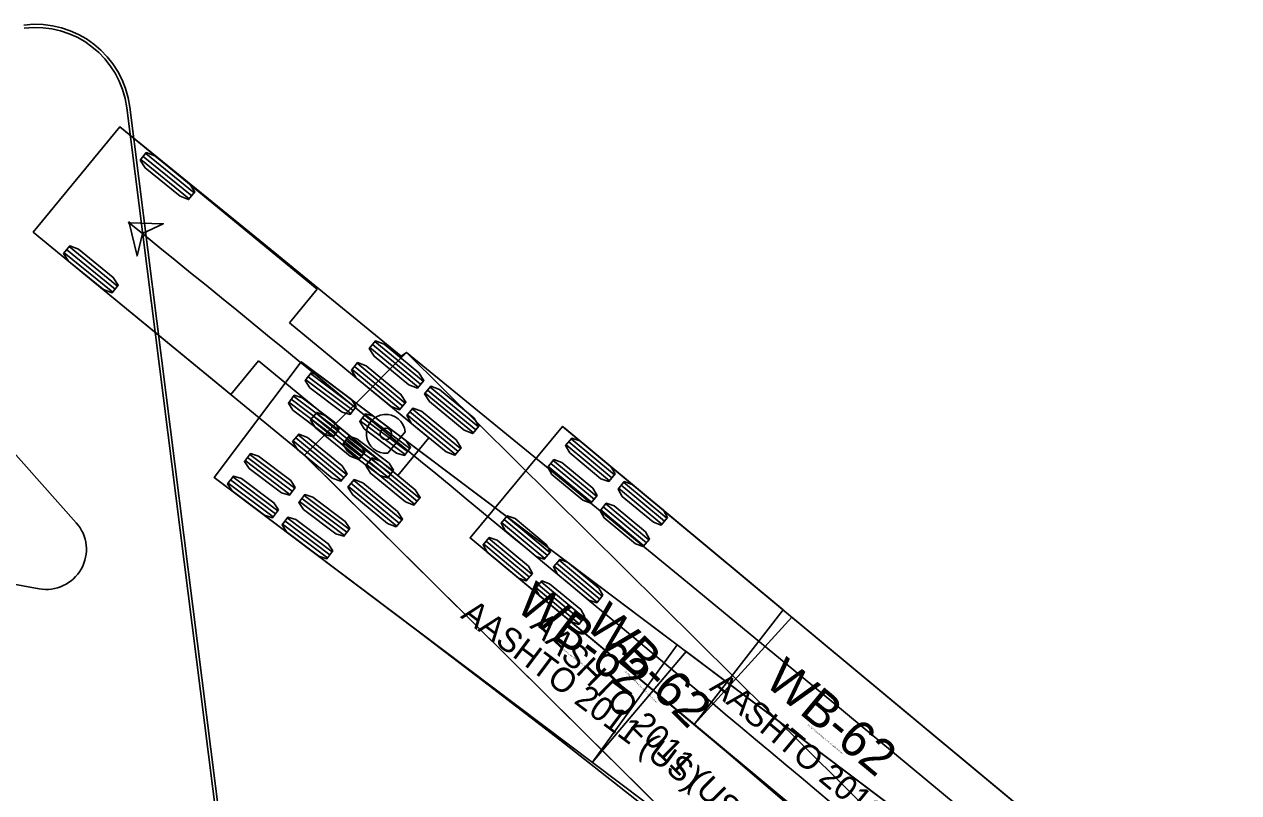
# Model space of a CAD drawing. Extents: x 2096670 to 2098561, y 684033 to 689893.
# Drawn here: x 2097513.6 to 2097584.9, y 686082 to 686127.1 of the extents above; entities that cross this region are included whole.
import ezdxf

# ---------------------------------------------------------------- set-up
doc = ezdxf.new("R2010")
doc.units = 0
doc.layers.add('Old_Level_63', color=7, linetype='Continuous')
doc.layers.add('Prop Sign E Keep Right CELL', color=7, linetype='Continuous')

# ---------------------------------------------------------------- blocks, each defined once
blk = doc.blocks.new('R4_7A')
at = {"layer": 'Prop Sign E Keep Right CELL'}
for points in [[(2.8414, 5.1147), (4.1564, 7.0314), (5.4711, 5.1147)], [(2.8414, 5.1147), (4.1564, 7.0314), (5.4711, 5.1147)], [(2.8414, 5.1147), (4.1564, 7.0314), (5.4711, 5.1147)], [(5.2458, 4.8106), (4.6564, 4.9975), (4.6564, 4.3867)], [(5.2458, 4.8106), (4.6564, 4.9975), (4.6564, 4.3867)], [(5.2458, 4.8106), (4.6564, 4.9975), (4.6564, 4.3867)]]:
    blk.add_lwpolyline(points, dxfattribs=at)
blk.add_arc((5.3062, 5.0014), 0.2, 252.39904, 34.44923, dxfattribs=at)
blk.add_arc((5.3062, 5.0014), 0.2, 252.39904, 34.44923, dxfattribs=at)
blk.add_arc((5.3062, 5.0014), 0.2, 252.39904, 34.44923, dxfattribs=at)

msp = doc.modelspace()

# ---------------------------------------------------------------- linework, layer by layer
at = {"layer": 'Old_Level_63'}
for p, q in [((2097519.23, 686121.097), (2097514.149, 686114.918)), ((2097530.816, 686111.569), (2097519.23, 686121.097)), ((2097520.748, 686119.537), (2097523.594, 686117.226)), ((2097520.459, 686119.182), (2097523.305, 686116.87)), ((2097520.604, 686119.359), (2097523.45, 686117.048)), ((2097514.149, 686114.918), (2097525.735, 686105.39)), ((2097514.149, 686114.918), (2097514.149, 686114.918)), ((2097516.109, 686113.885), (2097518.955, 686111.573)), ((2097516.253, 686114.063), (2097519.099, 686111.751)), ((2097515.964, 686113.707), (2097518.811, 686111.395)), ((2097529.186, 686109.587), (2097530.816, 686111.569)), ((2097537.373, 686102.854), (2097529.186, 686109.587)), ((2097533.907, 686108.137), (2097536.739, 686105.808)), ((2097534.052, 686108.314), (2097536.884, 686105.985)), ((2097534.198, 686108.491), (2097537.03, 686106.162)), ((2097536.055, 686107.859), (2097530.074, 686101.82)), ((2097570.158, 686074.08), (2097536.055, 686107.859)), ((2097529.882, 686107.308), (2097524.771, 686100.517)), ((2097525.735, 686105.39), (2097527.365, 686107.372)), ((2097527.365, 686107.372), (2097535.552, 686100.64)), ((2097568.235, 686078.446), (2097529.882, 686107.308)), ((2097532.859, 686106.863), (2097535.691, 686104.534)), ((2097533.004, 686107.04), (2097535.836, 686104.711)), ((2097533.15, 686107.217), (2097535.982, 686104.888)), ((2097532.784, 686104.264), (2097530.147, 686106.248)), ((2097532.922, 686104.447), (2097530.285, 686106.431)), ((2097533.06, 686104.63), (2097530.423, 686106.614)), ((2097532.068, 686103.312), (2097529.431, 686105.296)), ((2097537.151, 686105.47), (2097539.983, 686103.141)), ((2097537.296, 686105.647), (2097540.128, 686103.318)), ((2097537.442, 686105.824), (2097540.274, 686103.495)), ((2097531.792, 686102.945), (2097529.155, 686104.93)), ((2097531.93, 686103.128), (2097529.293, 686105.113)), ((2097530.455, 686103.941), (2097533.288, 686101.612)), ((2097530.601, 686104.118), (2097533.433, 686101.789)), ((2097530.747, 686104.295), (2097533.579, 686101.966)), ((2097536.118, 686102.042), (2097533.481, 686104.026)), ((2097536.256, 686102.225), (2097533.619, 686104.209)), ((2097536.102, 686104.195), (2097538.935, 686101.866)), ((2097536.248, 686104.372), (2097539.08, 686102.043)), ((2097536.394, 686104.549), (2097539.226, 686102.22)), ((2097535.98, 686101.859), (2097533.343, 686103.843)), ((2097534.951, 686101.943), (2097535.978, 686103.191)), ((2097545.219, 686103.511), (2097539.785, 686096.975)), ((2097582.131, 686072.828), (2097545.219, 686103.511)), ((2097529.407, 686102.666), (2097532.239, 686100.337)), ((2097529.553, 686102.843), (2097532.385, 686100.514)), ((2097529.699, 686103.02), (2097532.531, 686100.691)), ((2097534.988, 686100.54), (2097532.351, 686102.524)), ((2097535.126, 686100.723), (2097532.489, 686102.708)), ((2097535.264, 686100.906), (2097532.627, 686102.891)), ((2097535.552, 686100.64), (2097537.373, 686102.854)), ((2097547.971, 686100.33), (2097545.433, 686102.439)), ((2097548.117, 686100.506), (2097545.58, 686102.615)), ((2097548.264, 686100.682), (2097545.726, 686102.791)), ((2097529.492, 686099.889), (2097526.855, 686101.873)), ((2097530.074, 686101.82), (2097564.176, 686068.041)), ((2097530.074, 686101.82), (2097530.074, 686101.82)), ((2097529.216, 686099.523), (2097526.58, 686101.507)), ((2097529.354, 686099.706), (2097526.717, 686101.69)), ((2097533.699, 686101.273), (2097536.531, 686098.944)), ((2097533.845, 686101.45), (2097536.677, 686099.121)), ((2097533.991, 686101.627), (2097536.823, 686099.298)), ((2097546.916, 686099.061), (2097544.378, 686101.17)), ((2097547.063, 686099.237), (2097544.525, 686101.346)), ((2097547.209, 686099.413), (2097544.671, 686101.523)), ((2097524.771, 686100.517), (2097563.124, 686071.655)), ((2097528.362, 686098.388), (2097525.725, 686100.372)), ((2097528.5, 686098.571), (2097525.863, 686100.555)), ((2097532.943, 686100.353), (2097535.775, 686098.024)), ((2097528.224, 686098.204), (2097525.588, 686100.189)), ((2097532.651, 686099.999), (2097535.483, 686097.67)), ((2097532.797, 686100.176), (2097535.629, 686097.847)), ((2097551.047, 686097.773), (2097548.509, 686099.882)), ((2097551.193, 686097.949), (2097548.656, 686100.058)), ((2097551.34, 686098.125), (2097548.802, 686100.235)), ((2097532.413, 686097.118), (2097529.776, 686099.102)), ((2097532.55, 686097.301), (2097529.914, 686099.285)), ((2097532.688, 686097.484), (2097530.051, 686099.468)), ((2097550.285, 686096.856), (2097547.747, 686098.966)), ((2097531.696, 686096.165), (2097529.059, 686098.15)), ((2097544.471, 686096.119), (2097541.933, 686098.229)), ((2097549.992, 686096.504), (2097547.454, 686098.613)), ((2097550.139, 686096.68), (2097547.601, 686098.789)), ((2097531.42, 686095.799), (2097528.784, 686097.784)), ((2097531.558, 686095.982), (2097528.921, 686097.967)), ((2097544.178, 686095.767), (2097541.64, 686097.876)), ((2097544.324, 686095.943), (2097541.787, 686098.052)), ((2097539.785, 686096.975), (2097576.698, 686066.291)), ((2097543.27, 686094.674), (2097540.732, 686096.784)), ((2097543.416, 686094.85), (2097540.878, 686096.96)), ((2097543.123, 686094.498), (2097540.585, 686096.607)), ((2097547.254, 686093.21), (2097544.716, 686095.319)), ((2097547.4, 686093.386), (2097544.863, 686095.496)), ((2097547.547, 686093.562), (2097545.009, 686095.672)), ((2097546.199, 686091.941), (2097543.662, 686094.05)), ((2097546.346, 686092.117), (2097543.808, 686094.227)), ((2097546.492, 686092.293), (2097543.954, 686094.403))]:
    msp.add_line(p, q, dxfattribs=at)
for points in [[(2097584.998, 686044.723), (2097583.404, 686046.727), (2097581.779, 686048.717), (2097580.126, 686050.695), (2097578.445, 686052.66), (2097576.74, 686054.613), (2097575.011, 686056.553), (2097573.261, 686058.481), (2097571.491, 686060.398), (2097569.701, 686062.303), (2097566.071, 686066.08), (2097562.372, 686069.823), (2097529.929, 686101.954), (2097514.149, 686114.918), (2097519.231, 686121.096), (2097527.464, 686114.404), (2097535.745, 686107.627), (2097536.055, 686107.859), (2097544.485, 686100.976), (2097552.767, 686094.18), (2097561.031, 686087.366), (2097569.295, 686080.518), (2097582.641, 686069.376), (2097584.908, 686067.744)], [(2097519.779, 686115.466), (2097520.243, 686113.521), (2097520.555, 686114.836), (2097521.778, 686115.411), (2097519.779, 686115.466)], [(2097585.096, 686051.112), (2097583.426, 686052.737), (2097581.71, 686054.358), (2097579.95, 686055.976), (2097578.157, 686057.591), (2097574.109, 686061.15), (2097570.125, 686064.581), (2097565.889, 686068.195), (2097561.931, 686071.536), (2097557.638, 686075.093), (2097553.568, 686078.396), (2097549.464, 686081.665), (2097545.052, 686085.119), (2097540.845, 686088.362), (2097536.614, 686091.587), (2097524.771, 686100.517), (2097529.882, 686107.308), (2097530.017, 686107.206), (2097530.017, 686107.206)], [(2097530.017, 686107.206), (2097551.942, 686090.707), (2097546.972, 686083.809), (2097552.477, 686090.305), (2097566.308, 686079.896), (2097561.133, 686073.153), (2097566.842, 686079.494), (2097571.049, 686076.306), (2097573.119, 686074.695), (2097575.458, 686072.839), (2097577.526, 686071.164), (2097585.156, 686065.397)], [(2097586.455, 686053.84), (2097584.867, 686055.688), (2097583.237, 686057.526), (2097581.35, 686059.593), (2097579.637, 686061.417), (2097577.893, 686063.229), (2097576.122, 686065.027), (2097574.328, 686066.811), (2097572.27, 686068.813), (2097570.422, 686070.576), (2097568.556, 686072.326), (2097566.671, 686074.063), (2097564.771, 686075.784), (2097562.6, 686077.718), (2097558.676, 686081.136), (2097554.692, 686084.531), (2097550.393, 686088.144), (2097539.785, 686096.975), (2097545.219, 686103.511), (2097545.363, 686103.391), (2097545.363, 686103.391)], [(2097545.363, 686103.391), (2097558.167, 686092.748), (2097552.948, 686086.033), (2097558.681, 686092.32), (2097583.641, 686071.566), (2097585.653, 686069.858)]]:
    msp.add_lwpolyline(points, dxfattribs=at)
for points in [[(2097520.423, 686119.137), (2097520.784, 686119.581), (2097521.291, 686119.392), (2097523.34, 686117.727), (2097523.63, 686117.27), (2097523.269, 686116.826), (2097522.762, 686117.016), (2097520.713, 686118.68)], [(2097519.779, 686115.466), (2097520.243, 686113.521), (2097520.555, 686114.836), (2097521.778, 686115.411)], [(2097515.928, 686113.663), (2097516.289, 686114.107), (2097516.796, 686113.917), (2097518.845, 686112.253), (2097519.135, 686111.795), (2097518.775, 686111.351), (2097518.268, 686111.541), (2097516.218, 686113.205)], [(2097533.87, 686108.094), (2097534.234, 686108.535), (2097534.74, 686108.342), (2097536.779, 686106.666), (2097537.066, 686106.206), (2097536.702, 686105.765), (2097536.197, 686105.958), (2097534.157, 686107.634)], [(2097532.822, 686106.819), (2097533.186, 686107.261), (2097533.692, 686107.068), (2097535.731, 686105.391), (2097536.018, 686104.932), (2097535.654, 686104.49), (2097535.149, 686104.683), (2097533.109, 686106.36)], [(2097533.094, 686104.675), (2097532.75, 686104.218), (2097532.277, 686104.358), (2097530.379, 686105.787), (2097530.113, 686106.203), (2097530.457, 686106.66), (2097530.93, 686106.52), (2097532.828, 686105.091)], [(2097532.102, 686103.357), (2097531.758, 686102.9), (2097531.285, 686103.04), (2097529.387, 686104.469), (2097529.121, 686104.884), (2097529.465, 686105.341), (2097529.938, 686105.201), (2097531.836, 686103.772)], [(2097537.114, 686105.426), (2097537.478, 686105.868), (2097537.984, 686105.675), (2097540.023, 686103.998), (2097540.31, 686103.539), (2097539.946, 686103.097), (2097539.441, 686103.29), (2097537.401, 686104.967)], [(2097536.066, 686104.151), (2097536.43, 686104.593), (2097536.936, 686104.4), (2097538.975, 686102.723), (2097539.262, 686102.264), (2097538.898, 686101.822), (2097538.392, 686102.015), (2097536.353, 686103.692)], [(2097530.419, 686103.897), (2097530.783, 686104.339), (2097531.289, 686104.146), (2097533.328, 686102.469), (2097533.615, 686102.01), (2097533.251, 686101.568), (2097532.745, 686101.761), (2097530.706, 686103.438)], [(2097536.29, 686102.27), (2097535.946, 686101.813), (2097535.473, 686101.953), (2097533.575, 686103.382), (2097533.309, 686103.797), (2097533.653, 686104.254), (2097534.126, 686104.114), (2097536.024, 686102.686)], [(2097529.371, 686102.623), (2097529.735, 686103.064), (2097530.241, 686102.871), (2097532.28, 686101.195), (2097532.567, 686100.735), (2097532.203, 686100.294), (2097531.697, 686100.487), (2097529.658, 686102.163)], [(2097535.298, 686100.952), (2097534.954, 686100.495), (2097534.481, 686100.635), (2097532.583, 686102.063), (2097532.317, 686102.479), (2097532.661, 686102.936), (2097533.134, 686102.796), (2097535.032, 686101.367)], [(2097548.3, 686100.726), (2097547.934, 686100.286), (2097547.469, 686100.449), (2097545.642, 686101.967), (2097545.397, 686102.395), (2097545.762, 686102.835), (2097546.228, 686102.672), (2097548.055, 686101.154)], [(2097529.526, 686099.934), (2097529.182, 686099.477), (2097528.709, 686099.618), (2097526.811, 686101.046), (2097526.545, 686101.462), (2097526.889, 686101.919), (2097527.362, 686101.779), (2097529.261, 686100.35)], [(2097533.663, 686101.229), (2097534.027, 686101.671), (2097534.533, 686101.478), (2097536.572, 686099.801), (2097536.859, 686099.342), (2097536.495, 686098.9), (2097535.989, 686099.093), (2097533.95, 686100.77)], [(2097547.245, 686099.457), (2097546.88, 686099.017), (2097546.414, 686099.18), (2097544.587, 686100.699), (2097544.342, 686101.126), (2097544.708, 686101.566), (2097545.173, 686101.404), (2097547, 686099.885)], [(2097528.534, 686098.616), (2097528.19, 686098.159), (2097527.717, 686098.299), (2097525.819, 686099.728), (2097525.553, 686100.143), (2097525.897, 686100.6), (2097526.37, 686100.46), (2097528.269, 686099.032)], [(2097532.615, 686099.955), (2097532.979, 686100.397), (2097533.485, 686100.204), (2097535.524, 686098.527), (2097535.811, 686098.068), (2097535.447, 686097.626), (2097534.941, 686097.819), (2097532.902, 686099.496)], [(2097551.376, 686098.169), (2097551.01, 686097.729), (2097550.545, 686097.892), (2097548.718, 686099.411), (2097548.473, 686099.838), (2097548.838, 686100.278), (2097549.304, 686100.115), (2097551.131, 686098.597)], [(2097532.722, 686097.529), (2097532.378, 686097.072), (2097531.906, 686097.212), (2097530.007, 686098.641), (2097529.742, 686099.056), (2097530.086, 686099.514), (2097530.558, 686099.373), (2097532.457, 686097.945)], [(2097550.321, 686096.9), (2097549.956, 686096.46), (2097549.49, 686096.623), (2097547.663, 686098.142), (2097547.418, 686098.569), (2097547.784, 686099.009), (2097548.249, 686098.847), (2097550.076, 686097.328)], [(2097531.73, 686096.211), (2097531.386, 686095.754), (2097530.913, 686095.894), (2097529.015, 686097.323), (2097528.749, 686097.738), (2097529.093, 686098.195), (2097529.566, 686098.055), (2097531.465, 686096.626)], [(2097544.507, 686096.163), (2097544.142, 686095.723), (2097543.676, 686095.886), (2097541.849, 686097.405), (2097541.604, 686097.833), (2097541.97, 686098.272), (2097542.435, 686098.11), (2097544.262, 686096.591)], [(2097543.453, 686094.894), (2097543.087, 686094.454), (2097542.621, 686094.617), (2097540.794, 686096.136), (2097540.549, 686096.564), (2097540.915, 686097.004), (2097541.38, 686096.841), (2097543.207, 686095.322)], [(2097547.583, 686093.606), (2097547.218, 686093.166), (2097546.752, 686093.329), (2097544.925, 686094.848), (2097544.68, 686095.276), (2097545.046, 686095.715), (2097545.511, 686095.553), (2097547.338, 686094.034)], [(2097546.529, 686092.337), (2097546.163, 686091.897), (2097545.697, 686092.06), (2097543.87, 686093.579), (2097543.625, 686094.007), (2097543.991, 686094.447), (2097544.456, 686094.284), (2097546.283, 686092.765)]]:
    msp.add_lwpolyline(points, close=True, dxfattribs=at)
for centre, radius in [((2097519.779, 686115.466), 0.0417), ((2097534.841, 686103.081), 0.34)]:
    msp.add_circle(centre, radius, dxfattribs=at)
for centre, radius, start, end in [((2095488.549, 683614.496), 3221.917, 49.594378, 50.917298), ((2097534.841, 686103.081), 1.143, 5.56758, 275.56758)]:
    msp.add_arc(centre, radius, start, end, dxfattribs=at)
at = {"layer": 'Prop Sign E Keep Right CELL'}
for p, q in [((2097529.398, 686044.878), (2097519.635, 686122.215)), ((2097529.58, 686044.901), (2097519.818, 686122.238))]:
    msp.add_line(p, q, dxfattribs=at)
for radius in [5.568, 5.382]:
    msp.add_arc((2097514.295, 686121.541), radius, 7.19484, 97.19484, dxfattribs=at)

# ---------------------------------------------------------------- block references
at = {"layer": 'Prop Sign E Keep Right CELL', "xscale": 11.759366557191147, "yscale": 11.759366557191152, "rotation": 7.19484108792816}
msp.add_blockref('R4_7A', (2097460.373, 686030.137), dxfattribs=at)

# ---------------------------------------------------------------- texts
at = {"layer": 'Old_Level_63'}
for s, height, rotation, p in [('WB-62', 2.125, 323.03727, (2097542.36, 686092.812)), ('WB-62', 2.125, 315.27272, (2097546.461, 686091.81)), ('AASHTO 2011 (US)', 1.41667, 323.03727, (2097539.177, 686092.326)), ('AASHTO 2011 (US)', 1.41667, 315.27272, (2097543.241, 686091.759)), ('(c) 2023 Transoft Solutions, Inc. All rights reserved.', 0.085, 323.03727, (2097545.086, 686090.494)), ('WB-62', 2.125, 320.26486, (2097556.982, 686088.428)), ('(c) 2023 Transoft Solutions, Inc. All rights reserved.', 0.085, 315.27272, (2097548.849, 686089.145)), ('AASHTO 2011 (US)', 1.41667, 320.26486, (2097553.779, 686088.097)), ('(c) 2023 Transoft Solutions, Inc. All rights reserved.', 0.085, 320.26486, (2097559.593, 686085.981))]:
    msp.add_text(s, height=height, rotation=rotation, dxfattribs=at).set_placement(p)

doc.saveas('drawing.dxf')
